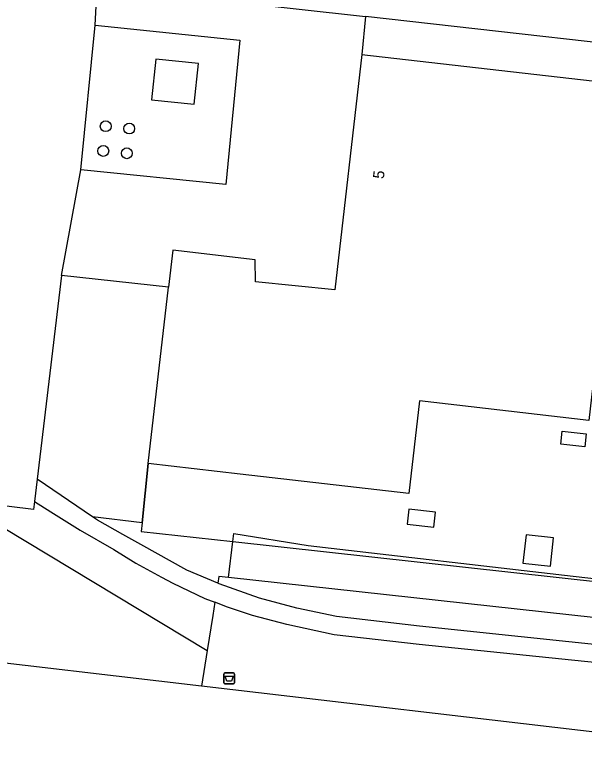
# Model space of a CAD drawing. Extents: x 161928 to 163055, y 386475 to 387428.
# Drawn here: x 162520.3 to 162572, y 386758.5 to 386825.3 of the extents above; entities that cross this region are included whole.
import ezdxf

# ---------------------------------------------------------------- set-up
doc = ezdxf.new("R2010")
doc.units = 0
for name, color, linetype in [('IMGEO_Afvalbak', 7, 'Continuous'), ('IMGEO_Boom', 7, 'Continuous'), ('IMGEO_Groenvoorziening', 7, 'Continuous'), ('IMGEO_Hek', 7, 'Continuous'), ('IMGEO_Lage_trafo', 7, 'Continuous'), ('IMGEO_Meer_plas_ven_vijver', 7, 'Continuous'), ('IMGEO_Pand', 7, 'Continuous'), ('IMGEO_Pand_nummerreeks', 7, 'Continuous'), ('IMGEO_Parkeervlak_open', 7, 'Continuous'), ('IMGEO_Voetpad_halfverhard', 7, 'Continuous'), ('IMGEO_Voetpad_open', 7, 'Continuous')]:
    doc.layers.add(name, color=color, linetype=linetype)

msp = doc.modelspace()

# ---------------------------------------------------------------- linework, layer by layer
at = {"layer": 'IMGEO_Afvalbak'}
for p, q in [((162539.255, 386764.669), (162539.255, 386765.469)), ((162539.255, 386765.469), (162539.255, 386764.669)), ((162539.355, 386765.569), (162540.145, 386765.569)), ((162540.145, 386765.569), (162539.355, 386765.569)), ((162540.245, 386765.469), (162540.245, 386764.669)), ((162540.245, 386764.669), (162540.245, 386765.469)), ((162540.145, 386764.569), (162539.355, 386764.569)), ((162539.355, 386764.569), (162540.145, 386764.569))]:
    msp.add_line(p, q, dxfattribs=at)
msp.add_lwpolyline([(162539.398, 386765.283), (162540.102, 386765.283), (162539.953, 386764.813), (162539.547, 386764.813), (162539.398, 386765.283)], dxfattribs=at)
for centre, start, end in [((162539.355, 386765.469), 90, 180), ((162539.355, 386765.469), 90, 180), ((162540.145, 386765.469), 0, 90), ((162540.145, 386765.469), 360, 90), ((162539.355, 386764.669), 180, 270), ((162539.355, 386764.669), 180, 270), ((162540.145, 386764.669), 270, 0), ((162540.145, 386764.669), 270, 0)]:
    msp.add_arc(centre, 0.1, start, end, dxfattribs=at)
at = {"layer": 'IMGEO_Boom'}
for centre in [(162528.54, 386815.178), (162530.679, 386814.967), (162528.32, 386812.938), (162530.459, 386812.727)]:
    msp.add_circle(centre, 0.489, dxfattribs=at)
at = {"layer": 'IMGEO_Groenvoorziening'}
for points in [[(162540.094, 386777.49), (162540.185, 386778.232), (162546.923, 386777.131), (162570.982, 386774.364), (162585.621, 386772.68), (162590.197, 386810.896)], [(162540.094, 386777.49), (162586.447, 386772.391), (162589.246, 386800.408), (162589.792, 386807.152), (162590.879, 386806.964), (162591.77, 386806.522), (162592.81, 386805.625), (162593.042, 386805.018), (162589.356, 386770.795)], [(162532.405, 386784.57), (162531.842, 386779.193)], [(162515.09, 386781.243), (162537.749, 386767.595)], [(162531.842, 386779.193), (162527.334, 386779.742)], [(162531.842, 386779.193), (162531.76, 386778.407), (162540.094, 386777.49)], [(162539.696, 386774.235), (162540.094, 386777.49)], [(162539.696, 386774.235), (162538.814, 386774.332), (162538.712, 386773.706)], [(162587.428, 386768.991), (162539.696, 386774.235)], [(162538.441, 386771.977), (162538.254, 386770.793), (162537.749, 386767.595)], [(162537.749, 386767.595), (162537.239, 386764.371)]]:
    msp.add_lwpolyline(points, dxfattribs=at)
at = {"layer": 'IMGEO_Hek'}
msp.add_lwpolyline([(162531.842, 386779.193), (162532.405, 386784.57)], dxfattribs=at)
at = {"layer": 'IMGEO_Lage_trafo'}
msp.add_lwpolyline([(162536.955, 386820.865), (162533.09, 386821.262), (162532.711, 386817.572), (162536.575, 386817.175), (162536.955, 386820.865)], dxfattribs=at)
at = {"layer": 'IMGEO_Meer_plas_ven_vijver'}
for points in [[(162537.239, 386764.371), (162513.461, 386767.162)], [(162588.496, 386758.549), (162574.505, 386760.001), (162537.239, 386764.371)]]:
    msp.add_lwpolyline(points, dxfattribs=at)
at = {"layer": 'IMGEO_Pand'}
for points in [[(162551.783, 386821.695), (162575.899, 386818.929), (162572.408, 386788.492), (162557.025, 386790.256), (162556.061, 386781.857), (162540.754, 386783.612), (162532.405, 386784.57)], [(162551.783, 386821.695), (162549.334, 386800.335), (162542.136, 386801.067), (162542.097, 386803.066), (162534.624, 386803.923), (162534.24, 386800.572)], [(162532.405, 386784.57), (162534.24, 386800.572)], [(162572.028, 386786.082), (162569.849, 386786.332), (162569.985, 386787.523), (162572.164, 386787.273), (162572.028, 386786.082)], [(162558.495, 386780.15), (162556.053, 386780.43), (162555.898, 386779.084), (162558.34, 386778.804), (162558.495, 386780.15)], [(162569.207, 386777.82), (162566.704, 386778.108), (162566.41, 386775.542), (162568.913, 386775.255), (162569.207, 386777.82)]]:
    msp.add_lwpolyline(points, dxfattribs=at)
at = {"layer": 'IMGEO_Parkeervlak_open'}
for points in [[(162552.129, 386825.148), (162551.783, 386821.695)], [(162527.584, 386824.351), (162540.722, 386822.998), (162539.457, 386809.906), (162526.291, 386811.228)], [(162534.24, 386800.572), (162524.527, 386801.638)]]:
    msp.add_lwpolyline(points, dxfattribs=at)
at = {"layer": 'IMGEO_Voetpad_halfverhard'}
for points in [[(162527.334, 386779.742), (162522.317, 386783.157)], [(162522.075, 386781.134), (162523.552, 386780.202), (162526.217, 386778.521), (162529.27, 386776.763), (162531.279, 386775.53), (162533.606, 386774.245), (162534.643, 386773.722), (162537.532, 386772.316), (162538.441, 386771.977)], [(162538.712, 386773.706), (162535.904, 386774.91), (162531.715, 386777.22), (162530.083, 386778.143), (162527.809, 386779.419), (162527.334, 386779.742)], [(162585.604, 386767.334), (162584.398, 386767.253), (162582.329, 386767.26), (162579.816, 386767.435), (162557.015, 386769.807), (162549.486, 386770.678), (162545.885, 386771.441), (162542.492, 386772.339), (162538.839, 386773.651), (162538.712, 386773.706)], [(162586.157, 386765.613), (162583.652, 386765.6), (162582.103, 386765.631), (162579.664, 386765.82), (162556.999, 386768.156), (162549.296, 386769.025), (162544.995, 386769.969), (162541.872, 386770.778), (162539.507, 386771.581), (162538.524, 386771.947), (162538.443, 386771.977), (162538.441, 386771.977)]]:
    msp.add_lwpolyline(points, dxfattribs=at)
at = {"layer": 'IMGEO_Voetpad_open'}
for points in [[(162527.584, 386824.351), (162527.763, 386827.865)], [(162527.763, 386827.865), (162552.129, 386825.148)], [(162590.957, 386820.768), (162586.471, 386821.274), (162552.129, 386825.148)], [(162526.291, 386811.228), (162527.584, 386824.351)], [(162524.527, 386801.638), (162526.291, 386811.228)], [(162524.527, 386801.638), (162522.317, 386783.157)], [(162522.317, 386783.157), (162522.075, 386781.134)], [(162522.075, 386781.134), (162521.987, 386780.399), (162515.09, 386781.243)]]:
    msp.add_lwpolyline(points, dxfattribs=at)

# ---------------------------------------------------------------- texts
at = {"layer": 'IMGEO_Pand_nummerreeks'}
msp.add_text('5', height=1, rotation=83.45939, dxfattribs=at).set_placement((162553.786, 386810.368))

doc.saveas('drawing.dxf')
